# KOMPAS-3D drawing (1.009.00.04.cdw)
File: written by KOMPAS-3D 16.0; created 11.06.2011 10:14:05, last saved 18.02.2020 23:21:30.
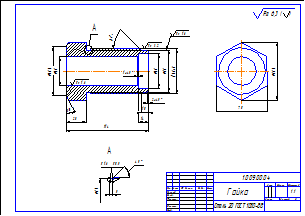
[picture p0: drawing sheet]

Sheet 1: A3, landscape

Title block, sheet 1: name: Гайка; designation: 1.009.00.04; material: Сталь 20 ГОСТ 1050-88; scale: 1:1; sheets: 1; sheet format: A4; stored path: C:\Users\Catonok\Desktop\Гайка.cdw

Views: Вид 1, Вид 2, Вид 3
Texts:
  Catonok
  Ra 1,6
  Ra 3,2
  Ra 6,3
  Ra 6,3 ( )
  Без боковой рамки
  Лит-Масса-Масштаб
  Материал-Предприятие
  Масштаб
  Изм.
  Лист
  № докум.
  Подп.
  Дата
  Лит.
  Разраб.
  Пров.
  Т.контр.
  Листов
  Н.контр.
  Утв.
  Изменение
  Номер документа
  Подпись
  Обозначение документа
  Наименование изделия
  Масса изделия по ГОСТ 2.109-73
  Порядковый номер листа
  Общее количество листов в документе
  Характер работы, выполненной лицом, подписавшим документ
  Наименование или индекс предприятия, выпускающего документ
Dimensions and other numbers on the sheet: 5; 57; 0,5; 1,6; 60; 80,6; 70; 28; 68,4; 40; 114; 10; 14; 2; 48; 1; 58; 1:1; 1.009.00.04; 1.009.00.04-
